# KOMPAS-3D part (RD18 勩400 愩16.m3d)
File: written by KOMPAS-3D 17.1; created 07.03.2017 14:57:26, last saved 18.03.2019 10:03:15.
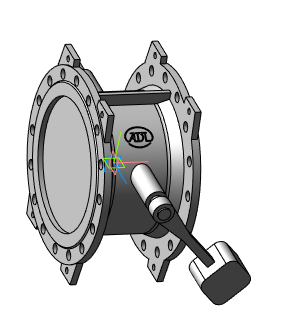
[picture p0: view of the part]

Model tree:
1. Операция без истории:2  (labels: Сталь 20  ГОСТ 1050-88)

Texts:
  RD18 Ду100 Ру16
  RD18 Ду150 Ру16
  RD18 Ду200 Ру16
  RD18 Ду250 Ру16
  RD18 Ду300 Ру16
  RD18 Ду350 Ру16
  RD18 Ду400 Ру10
  RD18 Ду400 Ру16
  RD18 Ду450 Ру10
  RD18 Ду450 Ру16
  RD18 Ду500 Ру10
  RD18 Ду500 Ру16
  RD18 Ду600 Ру10
  RD18 Ду600 Ру16
  RD18 Ду700 Ру10
  RD18 Ду700 Ру16
  RD18 Ду800 Ру10
  RD18 Ду800 Ру16
  RD18 Ду900 Ру10
  RD18 Ду900 Ру16
  RD18 Ду1000 Ру10
  RD18 Ду1000 Ру16
  RD18 Ду1200 Ру16
  RD18 Ду1400 Ру16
